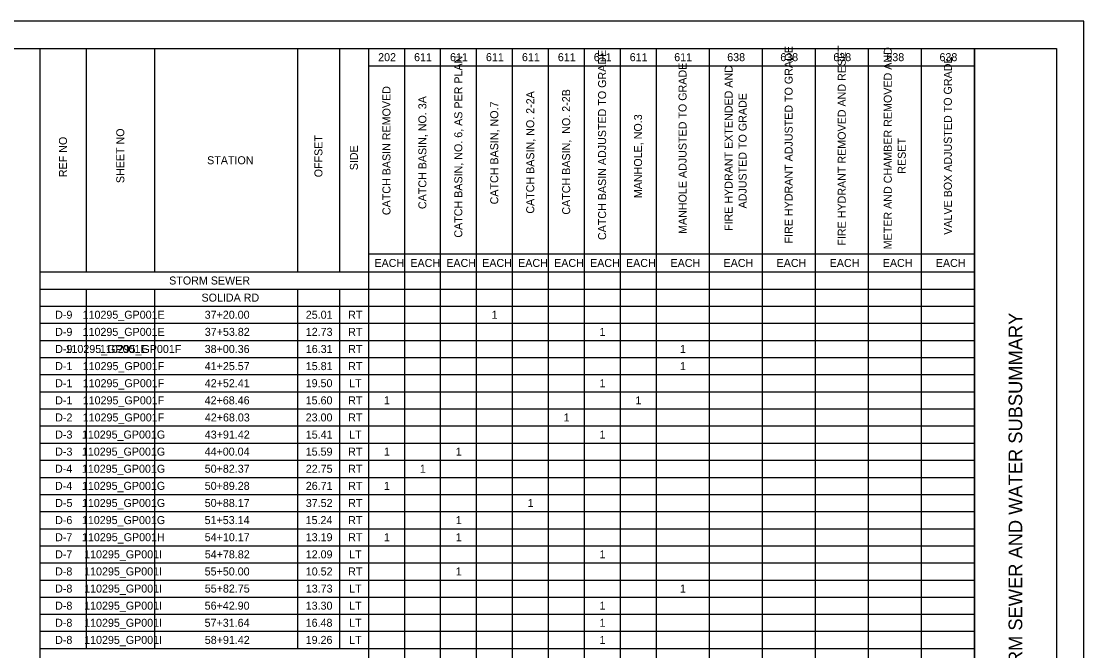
# Model space of a CAD drawing. Extents: x 0 to 34, y 0 to 22.
# Drawn here: x 14.57 to 34, y 10.49 to 22 of the extents above; entities that cross this region are included whole.
import ezdxf

# ---------------------------------------------------------------- set-up
doc = ezdxf.new("R2010")
doc.units = 0
for name, color, linetype in [('SH_Border', 7, 'Continuous'), ('SH_Cut_Line', 7, 'Continuous'), ('SH_Data', 7, 'Continuous'), ('SH_Text', 7, 'Continuous')]:
    doc.layers.add(name, color=color, linetype=linetype)

msp = doc.modelspace()

# ---------------------------------------------------------------- linework, layer by layer
at = {"layer": 'SH_Border'}
msp.add_line((32, 0.5), (32, 21.5), dxfattribs=at)
msp.add_lwpolyline([(1.5, 21.5), (33.5, 21.5), (33.5, 0.5), (1.5, 0.5)], close=True, dxfattribs=at)
at = {"layer": 'SH_Cut_Line'}
msp.add_lwpolyline([(0, 0), (34, 0), (34, 22), (0, 22)], close=True, dxfattribs=at)
at = {"layer": 'SH_Data'}
for p, q in [((14.912, 21.5), (32, 21.5)), ((14.912, 21.5), (14.912, 0.5)), ((15.757, 21.5), (15.757, 17.416)), ((17.009, 21.5), (17.009, 17.416)), ((19.622, 21.5), (19.622, 17.416)), ((20.389, 21.5), (20.389, 17.416)), ((20.921, 21.5), (20.921, 0.5)), ((21.578, 21.5), (21.578, 0.5)), ((22.235, 21.5), (22.235, 0.5)), ((22.893, 21.5), (22.893, 0.5)), ((23.55, 21.5), (23.55, 0.5)), ((24.207, 21.5), (24.207, 0.5)), ((24.864, 21.5), (24.864, 0.5)), ((25.522, 21.5), (25.522, 0.5)), ((26.179, 21.5), (26.179, 0.5)), ((27.149, 21.5), (27.149, 0.5)), ((28.119, 21.5), (28.119, 0.5)), ((29.089, 21.5), (29.089, 0.5)), ((30.06, 21.5), (30.06, 0.5)), ((31.03, 21.5), (31.03, 0.5)), ((32, 21.5), (32, 0.5)), ((20.921, 21.187), (32, 21.187)), ((20.921, 17.744), (32, 17.744)), ((14.912, 17.416), (32, 17.416)), ((14.912, 17.103), (32, 17.103)), ((15.757, 17.103), (15.757, 10.531)), ((17.009, 17.103), (17.009, 10.531)), ((19.622, 17.103), (19.622, 10.531)), ((20.389, 17.103), (20.389, 10.531)), ((14.912, 16.79), (32, 16.79)), ((14.912, 16.477), (32, 16.477)), ((14.912, 16.164), (32, 16.164)), ((14.912, 15.851), (32, 15.851)), ((14.912, 15.538), (32, 15.538)), ((14.912, 15.225), (32, 15.225)), ((14.912, 14.912), (32, 14.912)), ((14.912, 14.599), (32, 14.599)), ((14.912, 14.286), (32, 14.286)), ((14.912, 13.973), (32, 13.973)), ((14.912, 13.66), (32, 13.66)), ((14.912, 13.347), (32, 13.347)), ((14.912, 13.034), (32, 13.034)), ((14.912, 12.721), (32, 12.721)), ((14.912, 12.408), (32, 12.408)), ((14.912, 12.095), (32, 12.095)), ((14.912, 11.782), (32, 11.782)), ((14.912, 11.469), (32, 11.469)), ((14.912, 11.156), (32, 11.156)), ((14.912, 10.844), (32, 10.844)), ((14.912, 10.531), (32, 10.531))]:
    msp.add_line(p, q, dxfattribs=at)

# ---------------------------------------------------------------- texts
msp.add_text('STORM SEWER AND WATER SUBSUMMARY', height=0.25, rotation=90, dxfattribs=at).set_placement((32.875, 9.557))
at = {"layer": 'SH_Text'}
for s, height, p in [('202', 0.1463, (21.098, 21.27)), ('611', 0.1463, (21.755, 21.27)), ('611', 0.1463, (22.412, 21.27)), ('611', 0.1463, (23.069, 21.27)), ('611', 0.1463, (23.727, 21.27)), ('611', 0.1463, (24.384, 21.27)), ('611', 0.1463, (25.041, 21.27)), ('611', 0.1463, (25.698, 21.27)), ('611', 0.1463, (26.512, 21.27)), ('638', 0.1463, (27.481, 21.27)), ('638', 0.1463, (28.451, 21.27)), ('638', 0.1463, (29.421, 21.27)), ('638', 0.1463, (30.391, 21.27)), ('638', 0.1463, (31.362, 21.27)), ('STATION', 0.1463, (17.971, 19.385)), ('EACH', 0.1463, (21.03, 17.507)), ('EACH', 0.1463, (21.687, 17.507)), ('EACH', 0.1463, (22.344, 17.507)), ('EACH', 0.1463, (23.001, 17.507)), ('EACH', 0.1463, (23.658, 17.507)), ('EACH', 0.1463, (24.316, 17.507)), ('EACH', 0.1463, (24.973, 17.507)), ('EACH', 0.1463, (25.63, 17.507)), ('EACH', 0.1463, (26.444, 17.507)), ('EACH', 0.1463, (27.414, 17.507)), ('EACH', 0.1463, (28.384, 17.507)), ('EACH', 0.1463, (29.354, 17.507)), ('EACH', 0.1463, (30.325, 17.507)), ('EACH', 0.1463, (31.295, 17.507)), ('STORM SEWER', 0.14631, (17.277, 17.186)), ('SOLIDA RD', 0.1463, (17.868, 16.873)), ('D-9', 0.1463, (15.192, 16.56)), ('110295_GP001E', 0.14631, (15.694, 16.56)), ('37+20.00', 0.1463, (17.926, 16.56)), ('25.01', 0.1463, (19.775, 16.56)), ('RT', 0.1463, (20.55, 16.56)), ('1', 0.146, (23.174, 16.56)), ('D-9', 0.1463, (15.192, 16.247)), ('110295_GP001E', 0.14631, (15.694, 16.247)), ('37+53.82', 0.1463, (17.928, 16.247)), ('12.73', 0.1463, (19.775, 16.247)), ('RT', 0.1463, (20.55, 16.247)), ('1', 0.146, (25.146, 16.247)), ('D-9', 0.1463, (15.192, 15.934)), ('110295_GP001E', 0.14631, (15.381, 15.934)), ('110295_GP001F', 0.14631, (16.009, 15.934)), ('38+00.36', 0.1463, (17.926, 15.934)), ('16.31', 0.1463, (19.775, 15.934)), ('RT', 0.1463, (20.55, 15.934)), ('1', 0.146, (26.617, 15.934)), ('D-1', 0.1463, (15.192, 15.621)), ('110295_GP001F', 0.14631, (15.696, 15.621)), ('41+25.57', 0.1463, (17.927, 15.621)), ('15.81', 0.1463, (19.775, 15.621)), ('RT', 0.1463, (20.55, 15.621)), ('1', 0.146, (26.617, 15.621)), ('D-1', 0.1463, (15.192, 15.308)), ('110295_GP001F', 0.14631, (15.696, 15.308)), ('42+52.41', 0.1463, (17.928, 15.308)), ('19.50', 0.1463, (19.773, 15.308)), ('LT', 0.1463, (20.569, 15.308)), ('1', 0.146, (25.146, 15.308)), ('D-1', 0.1463, (15.192, 14.995)), ('110295_GP001F', 0.14631, (15.696, 14.995)), ('42+68.46', 0.1463, (17.926, 14.995)), ('15.60', 0.1463, (19.773, 14.995)), ('RT', 0.1463, (20.55, 14.995)), ('1', 0.146, (21.203, 14.995)), ('1', 0.146, (25.803, 14.995)), ('D-2', 0.1463, (15.192, 14.682)), ('110295_GP001F', 0.14631, (15.696, 14.682)), ('42+68.03', 0.1463, (17.929, 14.682)), ('23.00', 0.1463, (19.773, 14.682)), ('RT', 0.1463, (20.55, 14.682)), ('1', 0.146, (24.489, 14.682)), ('D-3', 0.1463, (15.193, 14.369)), ('110295_GP001G', 0.14631, (15.681, 14.369)), ('43+91.42', 0.1463, (17.928, 14.369)), ('15.41', 0.1463, (19.775, 14.369)), ('LT', 0.1463, (20.569, 14.369)), ('1', 0.146, (25.146, 14.369)), ('D-3', 0.1463, (15.193, 14.057)), ('110295_GP001G', 0.14631, (15.681, 14.057)), ('44+00.04', 0.1463, (17.925, 14.057)), ('15.59', 0.1463, (19.774, 14.057)), ('RT', 0.1463, (20.55, 14.057)), ('1', 0.146, (21.203, 14.057)), ('1', 0.146, (22.517, 14.057)), ('D-4', 0.1463, (15.189, 13.744)), ('110295_GP001G', 0.14631, (15.681, 13.744)), ('50+82.37', 0.1463, (17.927, 13.744)), ('22.75', 0.1463, (19.775, 13.744)), ('RT', 0.1463, (20.55, 13.744)), ('1', 0.146, (21.86, 13.744)), ('D-4', 0.1463, (15.189, 13.431)), ('110295_GP001G', 0.14631, (15.681, 13.431)), ('50+89.28', 0.1463, (17.927, 13.431)), ('26.71', 0.1463, (19.775, 13.431)), ('RT', 0.1463, (20.55, 13.431)), ('1', 0.146, (21.203, 13.431)), ('D-5', 0.1463, (15.193, 13.118)), ('110295_GP001G', 0.14631, (15.681, 13.118)), ('50+88.17', 0.1463, (17.927, 13.118)), ('37.52', 0.1463, (19.775, 13.118)), ('RT', 0.1463, (20.55, 13.118)), ('1', 0.146, (23.832, 13.118)), ('D-6', 0.1463, (15.191, 12.805)), ('110295_GP001G', 0.14631, (15.681, 12.805)), ('51+53.14', 0.1463, (17.925, 12.805)), ('15.24', 0.1463, (19.772, 12.805)), ('RT', 0.1463, (20.55, 12.805)), ('1', 0.146, (22.517, 12.805)), ('D-7', 0.1463, (15.191, 12.492)), ('110295_GP001H', 0.14631, (15.683, 12.492)), ('54+10.17', 0.1463, (17.927, 12.492)), ('13.19', 0.1463, (19.774, 12.492)), ('RT', 0.1463, (20.55, 12.492)), ('1', 0.146, (21.203, 12.492)), ('1', 0.146, (22.517, 12.492)), ('D-7', 0.1463, (15.191, 12.179)), ('110295_GP001I', 0.14631, (15.722, 12.179)), ('54+78.82', 0.1463, (17.928, 12.179)), ('12.09', 0.1463, (19.774, 12.179)), ('LT', 0.1463, (20.569, 12.179)), ('1', 0.146, (25.146, 12.179)), ('D-8', 0.1463, (15.191, 11.866)), ('110295_GP001I', 0.14631, (15.722, 11.866)), ('55+50.00', 0.1463, (17.926, 11.866)), ('10.52', 0.1463, (19.775, 11.866)), ('RT', 0.1463, (20.55, 11.866)), ('1', 0.146, (22.517, 11.866)), ('D-8', 0.1463, (15.191, 11.553)), ('110295_GP001I', 0.14631, (15.722, 11.553)), ('55+82.75', 0.1463, (17.928, 11.553)), ('13.73', 0.1463, (19.775, 11.553)), ('LT', 0.1463, (20.569, 11.553)), ('1', 0.146, (26.617, 11.553)), ('D-8', 0.1463, (15.191, 11.24)), ('110295_GP001I', 0.14631, (15.722, 11.24)), ('56+42.90', 0.1463, (17.926, 11.24)), ('13.30', 0.1463, (19.773, 11.24)), ('LT', 0.1463, (20.569, 11.24)), ('1', 0.146, (25.146, 11.24)), ('D-8', 0.1463, (15.191, 10.927)), ('110295_GP001I', 0.14631, (15.722, 10.927)), ('57+31.64', 0.1463, (17.925, 10.927)), ('16.48', 0.1463, (19.773, 10.927)), ('LT', 0.1463, (20.569, 10.927)), ('1', 0.146, (25.146, 10.927)), ('D-8', 0.1463, (15.191, 10.614)), ('110295_GP001I', 0.14631, (15.722, 10.614)), ('58+91.42', 0.1463, (17.928, 10.614)), ('19.26', 0.1463, (19.773, 10.614)), ('LT', 0.1463, (20.569, 10.614)), ('1', 0.146, (25.146, 10.614))]:
    msp.add_text(s, height=height, dxfattribs=at).set_placement(p)
for s, height, p in [('CATCH BASIN ADJUSTED TO GRADE', 0.14631, (25.266, 17.999)), ('FIRE HYDRANT ADJUSTED TO GRADE', 0.14631, (28.677, 17.937)), ('FIRE HYDRANT REMOVED AND RESET', 0.14631, (29.648, 17.897)), ('METER AND CHAMBER REMOVED AND ', 0.14631, (30.49, 17.83)), ('CATCH BASIN, NO. 6, AS PER PLAN', 0.14631, (22.637, 18.043)), ('MANHOLE ADJUSTED TO GRADE', 0.14631, (26.737, 18.111)), ('FIRE HYDRANT EXTENDED AND ', 0.14631, (27.579, 18.165)), ('VALVE BOX ADJUSTED TO GRADE', 0.14631, (31.588, 18.095)), ('CATCH BASIN REMOVED', 0.14631, (21.323, 18.455)), ('CATCH BASIN, NO. 3A', 0.14631, (21.98, 18.565)), ('CATCH BASIN, NO. 2-2A', 0.14631, (23.952, 18.481)), ('CATCH BASIN,  NO. 2-2B', 0.14631, (24.609, 18.464)), ('ADJUSTED TO GRADE', 0.14631, (27.835, 18.577)), ('CATCH BASIN, NO.7', 0.14631, (23.294, 18.651)), ('MANHOLE, NO.3', 0.14631, (25.923, 18.765)), ('SHEET NO', 0.1463, (16.456, 19.04)), ('REF NO', 0.1463, (15.408, 19.149)), ('OFFSET', 0.1463, (20.079, 19.147)), ('RESET', 0.1463, (30.746, 19.212)), ('SIDE', 0.1463, (20.728, 19.275))]:
    msp.add_text(s, height=height, rotation=90, dxfattribs=at).set_placement(p)

doc.saveas('drawing.dxf')
